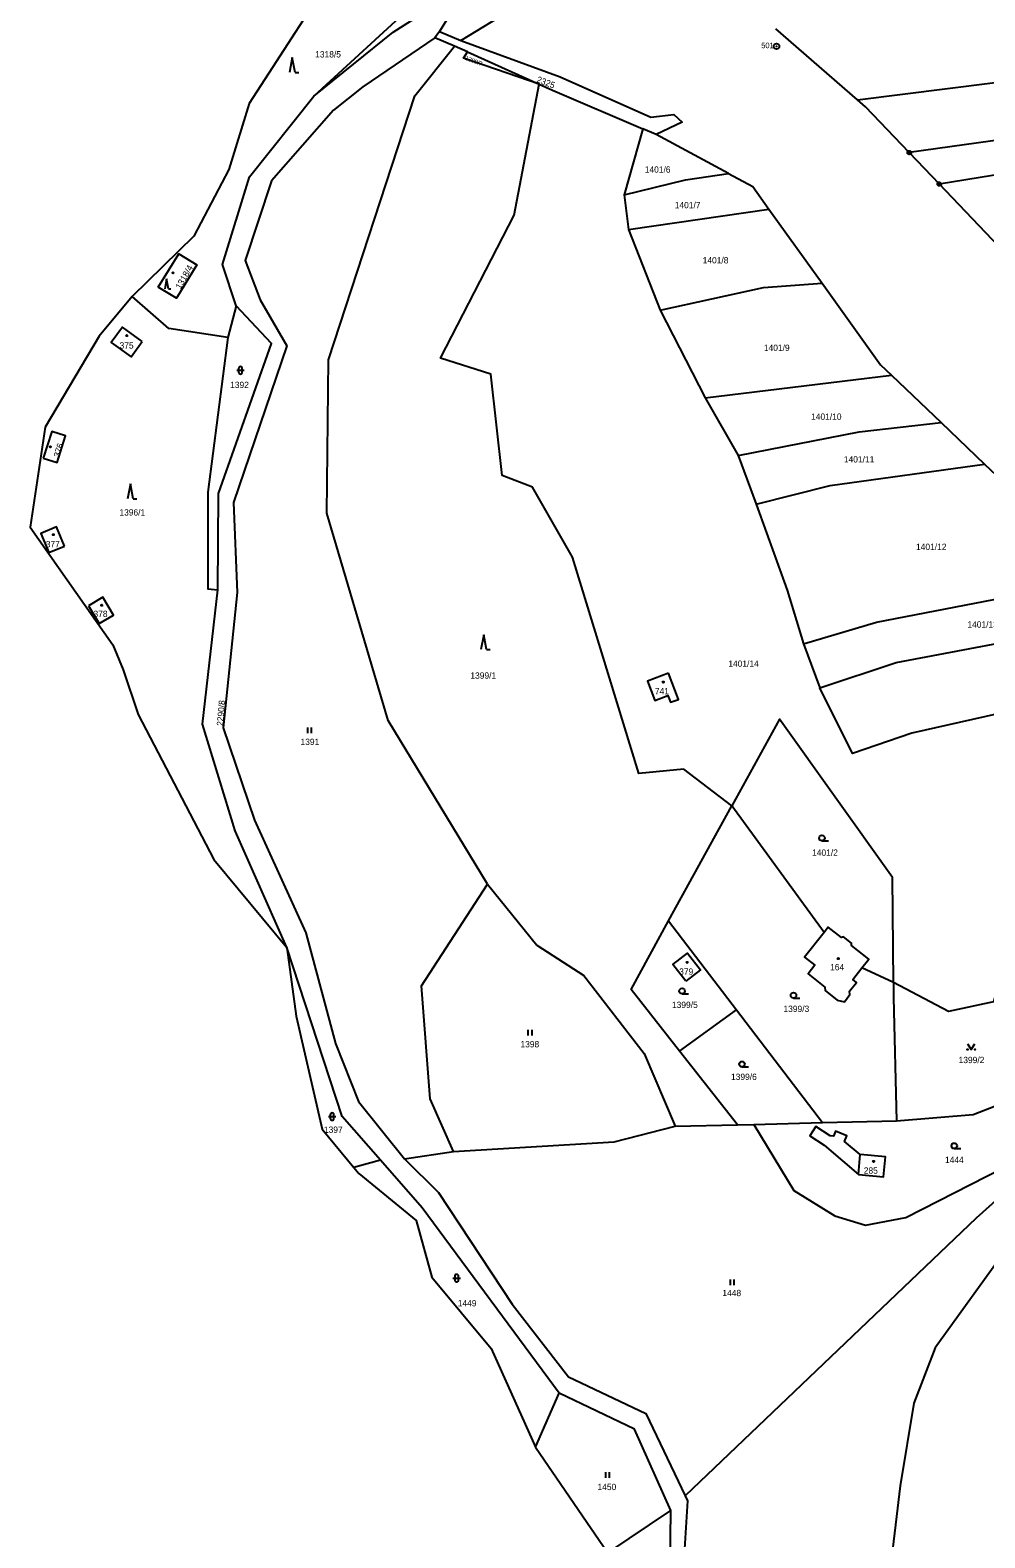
# Model space of a CAD drawing. Extents: x -725728 to -720881, y -1068679 to -1063504.
# Drawn here: x -723793.7 to -723536.2, y -1066046.1 to -1065639.6 of the extents above; entities that cross this region are included whole.
import ezdxf

# ---------------------------------------------------------------- set-up
doc = ezdxf.new("R2010")
doc.units = 0
for name, color, linetype in [('Hranice parcel', 7, 'Continuous'), ('Parcelní čísla', 7, 'Continuous'), ('Vnitřní kresba', 7, 'Continuous'), ('Značky bodu BP', 7, 'Continuous'), ('Značky budov', 7, 'Continuous'), ('Značky kultur', 7, 'Continuous')]:
    doc.layers.add(name, color=color, linetype=linetype)

# ---------------------------------------------------------------- blocks, each defined once
blk = doc.blocks.new('4.02_3')
at = {"layer": 'Značky budov'}
blk.add_circle((-0.001, 0), 0.0175, dxfattribs=at)
blk = doc.blocks.new('4.02_4')
at = {"layer": 'Značky budov'}
blk.add_circle((-0.001, 0), 0.0175, dxfattribs=at)
blk = doc.blocks.new('3.06_1')
at = {"layer": 'Značky kultur'}
for p, q in [((-0.051, 0), (-0.051, 0.15)), ((0.049, 0), (0.049, 0.15))]:
    blk.add_line(p, q, dxfattribs=at)
blk = doc.blocks.new('3.16_2')
at = {"layer": 'Značky kultur'}
for p, q in [((-0.1, 0.1), (0.1, 0.1)), ((-0.05, 0.15), (-0.05, 0.05)), ((0.05, 0.05), (0.05, 0.15))]:
    blk.add_line(p, q, dxfattribs=at)
for centre, start, end in [((0, 0.15), 0, 180), ((0, 0.05), 180, 359.9879)]:
    blk.add_arc(centre, 0.05, start, end, dxfattribs=at)
blk = doc.blocks.new('3.08_2')
at = {"layer": 'Značky kultur'}
for p, q in [((0, 0.4), (-0.075, 0)), ((0.075, 0), (0, 0.4)), ((0.075, 0), (0.175, 0))]:
    blk.add_line(p, q, dxfattribs=at)
blk = doc.blocks.new('3.08_1')
at = {"layer": 'Značky kultur'}
for p, q in [((0, 0.4), (-0.075, 0)), ((0.075, 0), (0, 0.4)), ((0.075, 0), (0.175, 0))]:
    blk.add_line(p, q, dxfattribs=at)
blk = doc.blocks.new('3.14_1')
at = {"layer": 'Značky kultur'}
blk.add_lwpolyline([(-0.1, 0.15), (0, 0), (0.1, 0.15)], dxfattribs=at)
for centre in [(-0.1, 0), (0.1, 0)]:
    blk.add_circle(centre, 0.01, dxfattribs=at)
blk = doc.blocks.new('3.04_2')
at = {"layer": 'Značky kultur'}
blk.add_line((0.001, 0), (0.176, 0), dxfattribs=at)
blk.add_circle((0.001, 0.075), 0.075, dxfattribs=at)
blk = doc.blocks.new('3.04_3')
at = {"layer": 'Značky kultur'}
blk.add_line((0.001, 0), (0.176, 0), dxfattribs=at)
blk.add_circle((0.001, 0.075), 0.075, dxfattribs=at)
blk = doc.blocks.new('3.06_2')
at = {"layer": 'Značky kultur'}
for p, q in [((-0.051, 0), (-0.051, 0.15)), ((0.049, 0), (0.049, 0.15))]:
    blk.add_line(p, q, dxfattribs=at)
blk = doc.blocks.new('3.08_3')
at = {"layer": 'Značky kultur'}
for p, q in [((0, 0.268), (-0.05, 0)), ((0.05, 0), (0, 0.268)), ((0.05, 0), (0.117, 0))]:
    blk.add_line(p, q, dxfattribs=at)
blk = doc.blocks.new('1.01_1')
at = {"layer": 'Značky bodu BP'}
for radius in [0.075, 0.003]:
    blk.add_circle((0, 0), radius, dxfattribs=at)
blk = doc.blocks.new('1.05_1')
at = {"layer": 'Značky bodu BP'}
for radius in [0.05, 0.00303]:
    blk.add_circle((0, 0), radius, dxfattribs=at)

msp = doc.modelspace()

# ---------------------------------------------------------------- linework, layer by layer
at = {"layer": 'Hranice parcel'}
for p, q in [((-723688.56, -1065631.06), (-723717.14, -1065657.4)), ((-723677.84, -1065631.17), (-723683.3, -1065639.96)), ((-723683.3, -1065639.96), (-723684.54, -1065641.67)), ((-723683.3, -1065639.96), (-723677.55, -1065642.33)), ((-723570.55, -1065658.33), (-723592.55, -1065639.19)), ((-723679.25, -1065643.89), (-723684.54, -1065641.67)), ((-723675.76, -1065645.46), (-723679.25, -1065643.89)), ((-723675.76, -1065645.46), (-723656.39, -1065654.17)), ((-723497.58, -1065664.22), (-723556.58, -1065672.6)), ((-723628.41, -1065666.2), (-723633.51, -1065684.01)), ((-723624.86, -1065667.71), (-723628.41, -1065666.2)), ((-723605.32, -1065678.23), (-723624.86, -1065667.71)), ((-723556.58, -1065672.6), (-723548.52, -1065681.06)), ((-723548.52, -1065681.06), (-723496.37, -1065672.46)), ((-723526.63, -1065704.04), (-723548.52, -1065681.06)), ((-723633.51, -1065684.01), (-723632.28, -1065693.33)), ((-723632.28, -1065693.33), (-723594.42, -1065687.85)), ((-723594.42, -1065687.85), (-723580.09, -1065707.84)), ((-723632.28, -1065693.33), (-723623.8, -1065715.07)), ((-723766.17, -1065711.38), (-723775.05, -1065722.08)), ((-723738.1, -1065713.96), (-723740.39, -1065722.46)), ((-723623.8, -1065715.07), (-723611.61, -1065738.71)), ((-723611.61, -1065738.71), (-723561.38, -1065732.65)), ((-723561.38, -1065732.65), (-723548, -1065745.41)), ((-723611.61, -1065738.71), (-723602.77, -1065754.27)), ((-723548, -1065745.41), (-723536.28, -1065756.6)), ((-723602.77, -1065754.27), (-723597.89, -1065767.39)), ((-723536.28, -1065756.6), (-723503.17, -1065788.19)), ((-723585.13, -1065805.06), (-723580.69, -1065816.96)), ((-723621.48, -1065879.8), (-723604.43, -1065848.71)), ((-723579.56, -1065882.88), (-723604.43, -1065848.71)), ((-723621.48, -1065879.8), (-723603.19, -1065903.75)), ((-723724.45, -1065886.94), (-723721.89, -1065905.46)), ((-723560.8, -1065896.37), (-723569.35, -1065892.43)), ((-723618.52, -1065914.9), (-723603.19, -1065903.75)), ((-723603.19, -1065903.75), (-723579.96, -1065934.17)), ((-723721.89, -1065905.46), (-723714.87, -1065935.96)), ((-723602.91, -1065934.75), (-723618.52, -1065914.9)), ((-723714.87, -1065935.96), (-723706.39, -1065946.25)), ((-723619.69, -1065935.17), (-723602.91, -1065934.75)), ((-723602.91, -1065934.75), (-723598.52, -1065934.64)), ((-723598.52, -1065934.64), (-723579.96, -1065934.17)), ((-723579.96, -1065934.17), (-723560.06, -1065933.66)), ((-723699.22, -1065944.27), (-723706.39, -1065946.25)), ((-723692.7, -1065943.96), (-723679.49, -1065942)), ((-723657.42, -1066021.66), (-723650.97, -1066007.15)), ((-723657.42, -1066021.66), (-723637.9, -1066050.19)), ((-723637.9, -1066050.19), (-723620.88, -1066038.78)), ((-723621.04, -1066053.65), (-723620.88, -1066038.78))]:
    msp.add_line(p, q, dxfattribs=at)
for points in [[(-723757.61, -1065571.42), (-723708.59, -1065619.15), (-723734.61, -1065659.33)], [(-723677.55, -1065642.33), (-723658.88, -1065630.98), (-723644.14, -1065612.07), (-723638.57, -1065588.05)], [(-723717.14, -1065657.4), (-723695.78, -1065640.12), (-723686.12, -1065634)], [(-723684.54, -1065641.67), (-723703.94, -1065654.89), (-723711.86, -1065661.14), (-723728.61, -1065680.21), (-723735.67, -1065701.65), (-723731.67, -1065712.29), (-723724.44, -1065724.72), (-723738.81, -1065766.95), (-723737.87, -1065791.21), (-723741.61, -1065827.72), (-723733.18, -1065852.57), (-723719.32, -1065883.03), (-723711.33, -1065912.81), (-723705.12, -1065928.47), (-723692.7, -1065943.96)], [(-723670.37, -1065869.89), (-723697.16, -1065825.76), (-723713.67, -1065769.84), (-723713.21, -1065728.48), (-723689.88, -1065657.32), (-723679.25, -1065643.89)], [(-723677.55, -1065642.33), (-723650.75, -1065652.17), (-723626.32, -1065663.03), (-723620.06, -1065662.35), (-723617.86, -1065664.41), (-723624.86, -1065667.71)], [(-723656.39, -1065654.17), (-723676.79, -1065647.15), (-723675.76, -1065645.46)], [(-723570.55, -1065658.33), (-723497.76, -1065649.2), (-723429.27, -1065645.13)], [(-723604.43, -1065848.71), (-723617.36, -1065838.86), (-723629.52, -1065840.04), (-723647.43, -1065781.69), (-723658.15, -1065762.85), (-723666.39, -1065759.71), (-723669.4, -1065732.37), (-723683, -1065728.05), (-723663.12, -1065689.46), (-723656.39, -1065654.17)], [(-723656.39, -1065654.17), (-723652.77, -1065655.8), (-723628.41, -1065666.2)], [(-723734.61, -1065659.33), (-723740.08, -1065677.16), (-723749.56, -1065695.14), (-723766.17, -1065711.38)], [(-723738.1, -1065713.96), (-723741.83, -1065702.74), (-723734.52, -1065679.17), (-723717.14, -1065657.4)], [(-723556.58, -1065672.6), (-723568.39, -1065660.21), (-723570.55, -1065658.33)], [(-723633.51, -1065684.01), (-723616.94, -1065679.9), (-723605.32, -1065678.23)], [(-723605.32, -1065678.23), (-723598.81, -1065681.73), (-723594.42, -1065687.85)], [(-723759.1, -1065708.87), (-723753.61, -1065699.88), (-723748.7, -1065702.87), (-723754.19, -1065711.86), (-723759.1, -1065708.87)], [(-723623.8, -1065715.07), (-723595.91, -1065708.97), (-723580.09, -1065707.84)], [(-723580.09, -1065707.84), (-723564.32, -1065729.85), (-723561.38, -1065732.65)], [(-723740.39, -1065722.46), (-723756.24, -1065720.07), (-723766.17, -1065711.38)], [(-723743.06, -1065790.47), (-723742.87, -1065764.49), (-723728.55, -1065724.08), (-723738.1, -1065713.96)], [(-723775.05, -1065722.08), (-723789.65, -1065746.63), (-723793.66, -1065773.56), (-723771.32, -1065805.37)], [(-723763.41, -1065723.49), (-723768.79, -1065719.64), (-723771.79, -1065723.83), (-723766.41, -1065727.68), (-723763.41, -1065723.49)], [(-723740.39, -1065722.46), (-723745.74, -1065764.2), (-723745.74, -1065790.27), (-723743.06, -1065790.47)], [(-723602.77, -1065754.27), (-723570.14, -1065747.86), (-723548, -1065745.41)], [(-723790.12, -1065754.95), (-723786.42, -1065756.14), (-723784.11, -1065749), (-723787.81, -1065747.8), (-723790.12, -1065754.95)], [(-723597.89, -1065767.39), (-723577.92, -1065762.35), (-723536.28, -1065756.6)], [(-723597.89, -1065767.39), (-723589.5, -1065790.57), (-723585.13, -1065805.06)], [(-723784.41, -1065778.69), (-723786.6, -1065773.52), (-723790.78, -1065775.3), (-723788.58, -1065780.47), (-723784.41, -1065778.69)], [(-723724.45, -1065886.94), (-723738.39, -1065855.52), (-723747.17, -1065826.76), (-723743.06, -1065790.47)], [(-723585.13, -1065805.06), (-723565.45, -1065799.26), (-723523.07, -1065791.03), (-723503.17, -1065788.19)], [(-723777.91, -1065794.81), (-723775.01, -1065799.62), (-723771.14, -1065797.29), (-723774.04, -1065792.48), (-723777.91, -1065794.81)], [(-723580.69, -1065816.96), (-723560.11, -1065810.09), (-723512.55, -1065801.09), (-723496.25, -1065799.1)], [(-723771.32, -1065805.37), (-723768.55, -1065812.05), (-723764.54, -1065824.09)], [(-723621.56, -1065812.99), (-723627.14, -1065815.13), (-723625.16, -1065820.31), (-723621.69, -1065818.98), (-723621, -1065820.78), (-723618.83, -1065820.1), (-723621.56, -1065812.99)], [(-723487.58, -1065815.51), (-723513.17, -1065819.55), (-723555.86, -1065829.16), (-723571.86, -1065834.65), (-723580.69, -1065816.96)], [(-723764.54, -1065824.09), (-723744.12, -1065863.25), (-723724.45, -1065886.94)], [(-723560.8, -1065896.37), (-723561.13, -1065868.06), (-723591.63, -1065825.39), (-723604.43, -1065848.71)], [(-723679.49, -1065942), (-723685.79, -1065927.73), (-723688.11, -1065897.32), (-723670.37, -1065869.89)], [(-723670.37, -1065869.89), (-723656.98, -1065886.3), (-723644.39, -1065894.5), (-723628.12, -1065915.53), (-723619.69, -1065935.17)], [(-723618.52, -1065914.9), (-723631.61, -1065898.26), (-723621.48, -1065879.8)], [(-723579.56, -1065882.88), (-723584.81, -1065889.57), (-723582.06, -1065891.73), (-723583.88, -1065894.05), (-723579.33, -1065897.64), (-723579.29, -1065898.57), (-723576.03, -1065901.13), (-723574.1, -1065901.56), (-723572.58, -1065899.58), (-723572.71, -1065898.76), (-723570.85, -1065896.35), (-723571.8, -1065895.62), (-723569.35, -1065892.43)], [(-723569.35, -1065892.43), (-723567.53, -1065890.07), (-723572.16, -1065886.42), (-723572.17, -1065885.78), (-723574.29, -1065884.11), (-723574.91, -1065884.25), (-723578.43, -1065881.48), (-723579.56, -1065882.88)], [(-723505.34, -1065881.13), (-723531.55, -1065893.54), (-723533.84, -1065901.62), (-723546.04, -1065904.22), (-723560.8, -1065896.37)], [(-723699.22, -1065944.27), (-723709.54, -1065932.53), (-723724.45, -1065886.94)], [(-723616.8, -1065896.07), (-723620.33, -1065891.54), (-723616.39, -1065888.46), (-723612.85, -1065892.99), (-723616.8, -1065896.07)], [(-723560.8, -1065896.37), (-723560.81, -1065900.47), (-723560.06, -1065933.66)], [(-723560.06, -1065933.66), (-723539.33, -1065931.98), (-723517.36, -1065923.45), (-723494.34, -1065909.1)], [(-723679.49, -1065942), (-723636.16, -1065939.34), (-723619.69, -1065935.17)], [(-723598.52, -1065934.64), (-723587.68, -1065952.5), (-723576.66, -1065959.31), (-723568.4, -1065961.78), (-723557.52, -1065959.75), (-723531.3, -1065946.33), (-723516.5, -1065936.22)], [(-723569.79, -1065942.8), (-723574.03, -1065939.29), (-723573.41, -1065937.75), (-723576.45, -1065936.49), (-723577.06, -1065937.81), (-723577.93, -1065937.75), (-723581.78, -1065935.26), (-723583.38, -1065937.73), (-723579.53, -1065940.22), (-723570.29, -1065948.19), (-723563.5, -1065948.79), (-723563.02, -1065943.4), (-723569.79, -1065942.8)], [(-723516.97, -1065940.64), (-723538.54, -1065959.93), (-723617.04, -1066034.8)], [(-723650.97, -1066007.15), (-723687.91, -1065957.13), (-723699.22, -1065944.27)], [(-723692.7, -1065943.96), (-723683.52, -1065953.06), (-723663.7, -1065983.11), (-723648.48, -1066002.76), (-723627.64, -1066012.63), (-723617.04, -1066034.8)], [(-723706.39, -1065946.25), (-723705.03, -1065947.9), (-723689.59, -1065960.55), (-723685.37, -1065975.86)], [(-723518.58, -1065955.58), (-723522.25, -1065957.07), (-723549.65, -1065994.94), (-723555.34, -1066009.84), (-723559.09, -1066032.13), (-723571.59, -1066137.3), (-723583.15, -1066153.73)], [(-723685.37, -1065975.86), (-723669.36, -1065995.12), (-723657.42, -1066021.66)], [(-723620.88, -1066038.78), (-723630.66, -1066016.81), (-723650.97, -1066007.15)], [(-723617.04, -1066034.8), (-723616.41, -1066036.12), (-723617.18, -1066049.06), (-723598.21, -1066076.89), (-723601.95, -1066086.76), (-723604.16, -1066099.27), (-723600.93, -1066104.71), (-723586.9, -1066120.12), (-723584.26, -1066137.47), (-723583.15, -1066153.73)]]:
    msp.add_lwpolyline(points, dxfattribs=at)
at = {"layer": 'Vnitřní kresba'}
msp.add_line((-723570.29, -1065948.19), (-723569.79, -1065942.8), dxfattribs=at)

# ---------------------------------------------------------------- block references
at = {"layer": 'Značky bodu BP', "xscale": 10, "yscale": 10}
for name, p in [('1.01_1', (-723592.39, -1065643.94)), ('1.05_1', (-723556.58, -1065672.6)), ('1.05_1', (-723548.52, -1065681.06))]:
    msp.add_blockref(name, p, dxfattribs=at)
at = {"layer": 'Značky budov', "xscale": 10, "yscale": 10}
for name, p in [('4.02_3', (-723755.11, -1065705.01)), ('4.02_3', (-723767.58, -1065721.95)), ('4.02_4', (-723788.23, -1065751.93)), ('4.02_3', (-723787.4, -1065775.62)), ('4.02_4', (-723774.36, -1065794.67)), ('4.02_4', (-723622.91, -1065815.38)), ('4.02_3', (-723616.47, -1065890.97)), ('4.02_3', (-723575.74, -1065889.95)), ('4.02_3', (-723566.21, -1065944.62))]:
    msp.add_blockref(name, p, dxfattribs=at)
at = {"layer": 'Značky kultur', "xscale": 10, "yscale": 10}
for name, p in [('3.08_1', (-723722.98, -1065650.98)), ('3.08_3', (-723756.87, -1065709.35)), ('3.16_2', (-723736.96, -1065732.3)), ('3.08_2', (-723766.63, -1065765.93)), ('3.08_1', (-723671.34, -1065806.62)), ('3.06_1', (-723718.28, -1065829.11)), ('3.04_3', (-723580.16, -1065858.18)), ('3.04_2', (-723617.87, -1065899.45)), ('3.04_2', (-723587.82, -1065900.59)), ('3.06_2', (-723658.81, -1065910.66)), ('3.14_1', (-723539.87, -1065914.44)), ('3.04_3', (-723601.71, -1065919.17)), ('3.16_2', (-723712.23, -1065933.54)), ('3.04_3', (-723544.47, -1065941.18)), ('3.16_2', (-723678.65, -1065977.11)), ('3.06_1', (-723604.27, -1065977.96)), ('3.06_1', (-723637.92, -1066029.97))]:
    msp.add_blockref(name, p, dxfattribs=at)

# ---------------------------------------------------------------- texts
at = {"layer": 'Parcelní čísla'}
for s, p in [('1318/5', (-723716.8, -1065646.94)), ('1401/6', (-723627.92, -1065678.01)), ('1401/7', (-723619.84, -1065687.6)), ('1401/8', (-723612.31, -1065702.48)), ('375', (-723769.55, -1065725.44)), ('1401/9', (-723595.8, -1065726.07)), ('1392', (-723739.73, -1065736.08)), ('1401/10', (-723583.07, -1065744.65)), ('1401/11', (-723574.23, -1065756.16)), ('1396/1', (-723769.58, -1065770.46)), ('377', (-723789.45, -1065779.03)), ('1401/12', (-723554.77, -1065779.75)), ('378', (-723776.58, -1065797.84)), ('1401/13', (-723540.91, -1065800.69)), ('1401/14', (-723605.39, -1065811.26)), ('1399/1', (-723674.95, -1065814.47)), ('741', (-723625.19, -1065818.67)), ('1391', (-723720.75, -1065832.34)), ('1401/2', (-723582.8, -1065862.22)), ('379', (-723618.64, -1065894.3)), ('164', (-723577.94, -1065893.1)), ('1399/5', (-723620.59, -1065903.26)), ('1399/3', (-723590.52, -1065904.33)), ('1398', (-723661.44, -1065913.87)), ('1399/2', (-723543.29, -1065918.13)), ('1399/6', (-723604.66, -1065922.66)), ('1397', (-723714.44, -1065936.93)), ('1444', (-723546.96, -1065945.05)), ('285', (-723568.86, -1065947.95)), ('1449', (-723678.35, -1065983.72)), ('1448', (-723606.99, -1065980.97)), ('1450', (-723640.66, -1066033.27))]:
    msp.add_text(s, height=1.7, dxfattribs=at).set_placement(p)
for s, height, rotation, p in [('1399/7', 1.14, 339, (-723676.47, -1065647.54)), ('2325', 1.7, 339, (-723657.24, -1065653.54)), ('1318/4', 1.7, 60, (-723753.13, -1065709.57)), ('376', 1.7, 73, (-723785.75, -1065754.91)), ('2290/8', 1.7, 85, (-723741.67, -1065827.27))]:
    msp.add_text(s, height=height, rotation=rotation, dxfattribs=at).set_placement(p)
at = {"layer": 'Značky bodu BP'}
msp.add_text('501', height=1.5, dxfattribs=at).set_placement((-723596.5, -1065644.44))

doc.saveas('drawing.dxf')
